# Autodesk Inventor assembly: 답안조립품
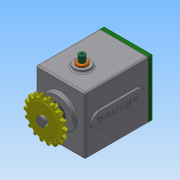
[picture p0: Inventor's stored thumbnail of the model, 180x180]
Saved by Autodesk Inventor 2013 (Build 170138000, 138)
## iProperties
Created: 2018-12
Part Number: 답안조립품
Document SubType Name: Assembly
Designer: Administrator
Mass: 2998.68 g
Surface Area: 1968.33 cm^2
Volume: 816.16 cm^3
Density: 3.67413 g/cm^3
Author: Administrator
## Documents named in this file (16)
- C:\Users\Administrator\Desktop\381207V1066\답안조립품.iam
- C:\Users\Administrator\Desktop\381207V1066\본체.ipt
- C:\Users\Administrator\Desktop\381207V1066\베어링 6003.ipt
- C:\Users\Administrator\Desktop\381207V1066\볼트 M4 x 10.ipt
- C:\Users\Administrator\Desktop\381207V1066\부시.ipt
- C:\Users\Administrator\Desktop\381207V1066\서브 기어 축.ipt
- C:\Users\Administrator\Desktop\381207V1066\스프로킷.ipt
- C:\Users\Administrator\Desktop\381207V1066\슬라이더.ipt
- C:\Users\Administrator\Desktop\381207V1066\오일 실 8 22 7.ipt
- C:\Users\Administrator\Desktop\381207V1066\오일 실 17 32 8.ipt
- C:\Users\Administrator\Desktop\381207V1066\커버.ipt
- C:\Users\Administrator\Desktop\381207V1066\키 5 x 5 x 18.ipt
- C:\Users\Administrator\Desktop\381207V1066\가변스프링.ipt
- C:\Users\Administrator\Desktop\381207V1066\멈춤나사 M3x8.ipt
- C:\Users\Administrator\Desktop\381207V1066\메인 기어 축.ipt
- C:\Users\Administrator\Desktop\381207V1066\베어링 608.ipt
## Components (1 placed, 1 different names)
1. 가변스프링:1
